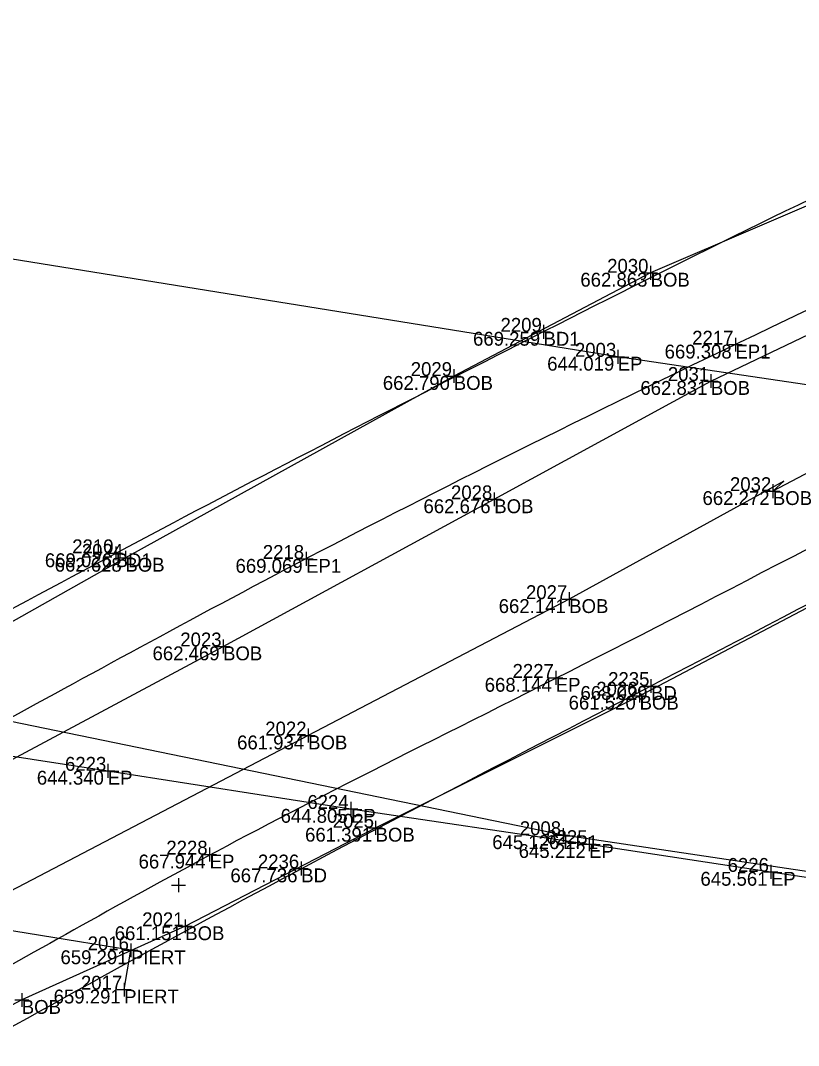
# Model space of a CAD drawing. Extents: x 2197382 to 2204062, y 634117 to 636522.
# Drawn here: x 2202828.1 to 2202884.1, y 635326 to 635399.9 of the extents above; entities that cross this region are included whole.
import ezdxf

# ---------------------------------------------------------------- set-up
doc = ezdxf.new("R2010")
doc.units = 0
for name, color, linetype in [('_CIVIL_CONSTRUCTION', 7, 'Continuous'), ('BR_X_SV_Bottom_of_Beam', 7, 'Continuous'), ('BR_X_SV_Bottom_of_Beam_Text', 7, 'Continuous'), ('BR_X_SV_Deck_Top', 7, 'Continuous'), ('BR_X_SV_Deck_Top_Text', 7, 'Continuous'), ('BR_X_SV_Pier', 7, 'Continuous'), ('BR_X_SV_Pier_Cap_Top_Text', 7, 'Continuous'), ('GE_P_Alignment_100_Distances', 7, 'Continuous'), ('SH_Border', 7, 'Continuous'), ('SH_Cut_Line', 7, 'Continuous'), ('SH_Data', 7, 'Continuous')]:
    doc.layers.add(name, color=color, linetype=linetype)

msp = doc.modelspace()

# ---------------------------------------------------------------- linework, layer by layer
at = {"layer": '_CIVIL_CONSTRUCTION'}
for p, q in [((2202873.474, 635382.191), (2202873.474, 635381.191)), ((2202872.974, 635381.691), (2202873.974, 635381.691)), ((2202873.474, 635381.691), (2202873.474, 635381.691)), ((2202865.758, 635377.935), (2202865.758, 635376.935)), ((2202865.258, 635377.435), (2202866.258, 635377.435)), ((2202865.758, 635377.435), (2202865.758, 635377.435)), ((2202879.585, 635377.009), (2202879.585, 635376.009)), ((2202871.103, 635376.135), (2202871.103, 635375.135)), ((2202879.085, 635376.509), (2202880.085, 635376.509)), ((2202879.585, 635376.509), (2202879.585, 635376.509)), ((2202870.603, 635375.635), (2202871.603, 635375.635)), ((2202871.103, 635375.635), (2202871.103, 635375.635)), ((2202859.286, 635374.749), (2202859.286, 635373.749)), ((2202858.786, 635374.249), (2202859.786, 635374.249)), ((2202859.286, 635374.249), (2202859.286, 635374.249)), ((2202877.318, 635373.889), (2202878.318, 635373.889)), ((2202877.818, 635374.389), (2202877.818, 635373.389)), ((2202877.818, 635373.889), (2202877.818, 635373.889)), ((2202882.287, 635366.45), (2202882.287, 635365.45)), ((2202862.206, 635365.861), (2202862.206, 635364.861)), ((2202881.787, 635365.95), (2202882.787, 635365.95)), ((2202882.287, 635365.95), (2202882.287, 635365.95)), ((2202861.706, 635365.361), (2202862.706, 635365.361)), ((2202862.206, 635365.361), (2202862.206, 635365.361)), ((2202834.415, 635361.468), (2202835.415, 635361.468)), ((2202834.915, 635361.968), (2202834.915, 635360.968)), ((2202834.915, 635361.468), (2202834.915, 635361.468)), ((2202835.616, 635361.644), (2202835.616, 635360.644)), ((2202848.639, 635361.563), (2202848.639, 635360.563)), ((2202835.116, 635361.144), (2202836.116, 635361.144)), ((2202835.616, 635361.144), (2202835.616, 635361.144)), ((2202848.139, 635361.063), (2202849.139, 635361.063)), ((2202848.639, 635361.063), (2202848.639, 635361.063)), ((2202867.606, 635358.664), (2202867.606, 635357.664)), ((2202867.106, 635358.164), (2202868.106, 635358.164)), ((2202867.606, 635358.164), (2202867.606, 635358.164)), ((2202842.156, 635354.754), (2202843.156, 635354.754)), ((2202842.656, 635355.254), (2202842.656, 635354.254)), ((2202842.656, 635354.754), (2202842.656, 635354.754)), ((2202866.138, 635352.488), (2202867.138, 635352.488)), ((2202866.638, 635352.988), (2202866.638, 635351.988)), ((2202866.638, 635352.488), (2202866.638, 635352.488)), ((2202873.502, 635352.401), (2202873.502, 635351.401)), ((2202872.681, 635351.702), (2202872.681, 635350.702)), ((2202873.002, 635351.901), (2202874.002, 635351.901)), ((2202873.502, 635351.901), (2202873.502, 635351.901)), ((2202872.181, 635351.202), (2202873.181, 635351.202)), ((2202872.681, 635351.202), (2202872.681, 635351.202)), ((2202848.789, 635348.833), (2202848.789, 635347.833)), ((2202848.289, 635348.333), (2202849.289, 635348.333)), ((2202848.789, 635348.333), (2202848.789, 635348.333)), ((2202833.846, 635345.79), (2202834.846, 635345.79)), ((2202834.346, 635346.29), (2202834.346, 635345.29)), ((2202834.346, 635345.79), (2202834.346, 635345.79)), ((2202851.873, 635343.542), (2202851.873, 635342.542)), ((2202851.373, 635343.042), (2202852.373, 635343.042)), ((2202851.873, 635343.042), (2202851.873, 635343.042)), ((2202853.649, 635342.182), (2202853.649, 635341.182)), ((2202853.149, 635341.682), (2202854.149, 635341.682)), ((2202853.649, 635341.682), (2202853.649, 635341.682)), ((2202867.163, 635341.647), (2202867.163, 635340.647)), ((2202866.663, 635341.147), (2202867.663, 635341.147)), ((2202867.163, 635341.147), (2202867.163, 635341.147)), ((2202869.038, 635341.006), (2202869.038, 635340.006)), ((2202841.688, 635340.248), (2202841.688, 635339.248)), ((2202868.538, 635340.506), (2202869.538, 635340.506)), ((2202869.038, 635340.506), (2202869.038, 635340.506)), ((2202841.188, 635339.748), (2202842.188, 635339.748)), ((2202841.688, 635339.748), (2202841.688, 635339.748)), ((2202848.289, 635339.249), (2202848.289, 635338.249)), ((2202847.789, 635338.749), (2202848.789, 635338.749)), ((2202848.289, 635338.749), (2202848.289, 635338.749)), ((2202881.647, 635338.503), (2202882.647, 635338.503)), ((2202882.147, 635339.003), (2202882.147, 635338.003)), ((2202882.147, 635338.503), (2202882.147, 635338.503)), ((2202839.444, 635338.041), (2202839.444, 635337.041)), ((2202838.944, 635337.541), (2202839.944, 635337.541)), ((2202839.444, 635337.541), (2202839.444, 635337.541)), ((2202839.929, 635335.08), (2202839.929, 635334.08)), ((2202839.429, 635334.58), (2202840.429, 635334.58)), ((2202839.929, 635334.58), (2202839.929, 635334.58)), ((2202836.019, 635333.348), (2202836.019, 635332.348)), ((2202835.519, 635332.848), (2202836.519, 635332.848)), ((2202836.019, 635332.848), (2202836.019, 635332.848)), ((2202835.527, 635330.515), (2202835.527, 635329.515)), ((2202828.147, 635329.766), (2202828.147, 635328.766)), ((2202835.027, 635330.015), (2202836.027, 635330.015)), ((2202835.527, 635330.015), (2202835.527, 635330.015)), ((2202827.647, 635329.266), (2202828.647, 635329.266)), ((2202828.147, 635329.266), (2202828.147, 635329.266))]:
    msp.add_line(p, q, dxfattribs=at)
at = {"layer": 'BR_X_SV_Bottom_of_Beam'}
for points in [[(2202895.149, 635391.277), (2202889.677, 635388.632), (2202873.474, 635381.691), (2202859.286, 635374.249), (2202835.616, 635361.144), (2202806.729, 635344.852)], [(2202811.504, 635338.061), (2202842.656, 635354.754), (2202862.206, 635365.361), (2202877.818, 635373.889), (2202891.444, 635380.393), (2202905.562, 635386.459), (2202910.377, 635388.736)], [(2202924.395, 635385.96), (2202919.465, 635383.68), (2202908.362, 635378.917), (2202897.213, 635373.813), (2202882.287, 635365.95), (2202883.082, 635366.661), (2202867.606, 635358.164), (2202848.789, 635348.333), (2202824.632, 635335.716)], [(2202839.929, 635334.58), (2202853.649, 635341.682), (2202872.681, 635351.202), (2202889.893, 635360.25), (2202903.168, 635366.923), (2202912.818, 635371.819), (2202920.337, 635375.101), (2202932.959, 635380.969), (2202937.114, 635382.149)], [(2202839.929, 635334.58), (2202828.147, 635329.266), (2202805.783, 635317.402), (2202793.121, 635309.278), (2202781.892, 635302.295), (2202770.512, 635294.985), (2202760.016, 635288.483), (2202748.947, 635281.46), (2202738.904, 635275.242), (2202730.251, 635269.14), (2202720.215, 635262.08), (2202711.743, 635255.569)]]:
    msp.add_lwpolyline(points, dxfattribs=at)
at = {"layer": 'BR_X_SV_Deck_Top'}
for points in [[(2202895.365, 635391.811), (2202885.347, 635387.334), (2202865.192, 635377.205), (2202839.037, 635363.762), (2202813.103, 635349.723), (2202789.18, 635336.138), (2202762.388, 635320.287), (2202740.668, 635306.565), (2202716.628, 635290.831), (2202693.394, 635275.343), (2202664.567, 635254.787), (2202633.536, 635231.765), (2202595.89, 635201.643), (2202569.397, 635178.622), (2202555.165, 635165.675)], [(2202923.181, 635376.197), (2202906.167, 635369.085), (2202881.487, 635355.934), (2202846.739, 635338.13), (2202819.013, 635322.649), (2202790.142, 635306.09), (2202754.022, 635283.778), (2202709.422, 635255.583), (2202663.285, 635220.884), (2202620.566, 635187.914), (2202595.285, 635167.396), (2202582.509, 635156.81)]]:
    msp.add_open_spline(points, degree=3, dxfattribs=at)
at = {"layer": 'BR_X_SV_Pier'}
msp.add_lwpolyline([(2202835.527, 635330.015), (2202836.019, 635332.848), (2202822.953, 635334.97), (2202822.999, 635334.938), (2202809.828, 635337.015), (2202809.889, 635336.977)], dxfattribs=at)
at = {"layer": 'GE_P_Alignment_100_Distances'}
for points in [[(2202975.789, 635361.358), (2202911.398, 635369.868), (2202894.289, 635372.201), (2202871.103, 635375.635), (2202823.555, 635383.286), (2202728.393, 635399.878)], [(2202937.002, 635329.713), (2202895.665, 635336.892), (2202867.163, 635341.147), (2202804.916, 635353.945)], [(2202818.285, 635348.253), (2202834.346, 635345.79), (2202851.873, 635343.042), (2202869.038, 635340.506), (2202882.147, 635338.503), (2202898.089, 635336.111), (2202910.08, 635334.482), (2202925.462, 635332.351), (2202937.945, 635330.578), (2202955.924, 635328.277)]]:
    msp.add_lwpolyline(points, dxfattribs=at)
for points in [[(2202926.993, 635398.223), (2202911.054, 635391.267), (2202884.78, 635379.221), (2202850.251, 635362.173), (2202828.215, 635350.038), (2202808.09, 635339.198), (2202790.855, 635329.045), (2202764, 635313.325), (2202738.781, 635297.635), (2202713.051, 635280.577), (2202697.019, 635269.602), (2202684.529, 635260.864), (2202668.986, 635249.754), (2202642.65, 635230.806), (2202596.561, 635193.887), (2202560.681, 635163.156), (2202538.312, 635142.813)], [(2202919.499, 635378.368), (2202901.447, 635370.678), (2202875.936, 635356.879), (2202844.592, 635341.598), (2202825.856, 635330.823), (2202809.466, 635322.019), (2202780.051, 635304.409), (2202746.062, 635282.999), (2202707.717, 635258.176), (2202682.244, 635240.209), (2202658.947, 635222.257), (2202614.143, 635189.251), (2202577.354, 635157.516), (2202549.508, 635131.427)]]:
    msp.add_open_spline(points, degree=3, dxfattribs=at)

# ---------------------------------------------------------------- texts
at = {"layer": 'BR_X_SV_Bottom_of_Beam_Text'}
for s, p in [('2030', (2202870.342, 635381.691)), ('662.863', (2202868.41, 635380.691)), ('BOB', (2202873.474, 635380.691)), ('2029', (2202856.184, 635374.249)), ('2031', (2202874.718, 635373.889)), ('662.790', (2202854.172, 635373.249)), ('BOB', (2202859.286, 635373.249)), ('662.831', (2202872.736, 635372.889)), ('BOB', (2202877.818, 635372.889)), ('2032', (2202879.195, 635365.95)), ('2028', (2202859.087, 635365.361)), ('662.272', (2202877.214, 635364.95)), ('BOB', (2202882.287, 635364.95)), ('662.676', (2202857.102, 635364.361)), ('BOB', (2202862.206, 635364.361)), ('2024', (2202832.475, 635361.144)), ('662.628', (2202830.516, 635360.144)), ('BOB', (2202835.616, 635360.144)), ('2027', (2202864.491, 635358.164)), ('662.141', (2202862.524, 635357.164)), ('BOB', (2202867.606, 635357.164)), ('2023', (2202839.573, 635354.754)), ('662.469', (2202837.572, 635353.754)), ('BOB', (2202842.656, 635353.754)), ('2026', (2202869.558, 635351.202)), ('661.520', (2202867.567, 635350.202)), ('BOB', (2202872.681, 635350.202)), ('2022', (2202845.697, 635348.333)), ('661.934', (2202843.667, 635347.333)), ('BOB', (2202848.789, 635347.333)), ('2025', (2202850.56, 635341.682)), ('661.391', (2202848.567, 635340.682)), ('BOB', (2202853.649, 635340.682)), ('2021', (2202836.829, 635334.58)), ('661.151', (2202834.847, 635333.58)), ('BOB', (2202839.929, 635333.58)), ('BOB', (2202828.147, 635328.266))]:
    msp.add_text(s, height=1, dxfattribs=at).set_placement(p)
at = {"layer": 'BR_X_SV_Deck_Top_Text'}
for s, p in [('2209', (2202862.656, 635377.435)), ('669.259', (2202860.674, 635376.435)), ('BD1', (2202865.758, 635376.435)), ('2210', (2202831.783, 635361.468)), ('669.026', (2202829.811, 635360.468)), ('BD1', (2202834.915, 635360.468)), ('2235', (2202870.413, 635351.901)), ('668.029', (2202868.418, 635350.901)), ('BD', (2202873.502, 635350.901)), ('2236', (2202845.166, 635338.749)), ('667.736', (2202843.185, 635337.749)), ('BD', (2202848.289, 635337.749))]:
    msp.add_text(s, height=1, dxfattribs=at).set_placement(p)
at = {"layer": 'BR_X_SV_Pier_Cap_Top_Text'}
for s, p in [('2016', (2202832.896, 635332.848)), ('659.291', (2202830.937, 635331.848)), ('PIERT', (2202836.019, 635331.848)), ('2017', (2202832.412, 635330.015)), ('659.291', (2202830.445, 635329.015)), ('PIERT', (2202835.527, 635329.015))]:
    msp.add_text(s, height=1, dxfattribs=at).set_placement(p)
at = {"layer": 'SH_Border'}
for s, p in [('EP1', (2202879.585, 635375.509)), ('EP', (2202871.103, 635374.635)), ('EP1', (2202848.639, 635360.063)), ('EP', (2202866.638, 635351.488)), ('EP', (2202834.346, 635344.79)), ('EP', (2202851.873, 635342.042)), ('EP1', (2202867.163, 635340.147)), ('EP', (2202869.038, 635339.506)), ('EP', (2202841.688, 635338.748)), ('EP', (2202882.147, 635337.503))]:
    msp.add_text(s, height=1, dxfattribs=at).set_placement(p)
at = {"layer": 'SH_Cut_Line'}
for s, p in [('2217', (2202876.47, 635376.509)), ('2003', (2202868.02, 635375.635)), ('2218', (2202845.52, 635361.063)), ('2227', (2202863.523, 635352.488)), ('6223', (2202831.263, 635345.79)), ('6224', (2202848.732, 635343.042)), ('2008', (2202864.044, 635341.147)), ('6225', (2202865.949, 635340.506)), ('2228', (2202838.569, 635339.748)), ('6226', (2202879.024, 635338.503))]:
    msp.add_text(s, height=1, dxfattribs=at).set_placement(p)
at = {"layer": 'SH_Data'}
for s, p in [('669.308', (2202874.485, 635375.509)), ('644.019', (2202866.019, 635374.635)), ('669.069', (2202843.555, 635360.063)), ('668.144', (2202861.516, 635351.488)), ('644.340', (2202829.232, 635344.79)), ('644.805', (2202846.803, 635342.042)), ('645.126', (2202862.059, 635340.147)), ('645.212', (2202863.965, 635339.506)), ('667.944', (2202836.566, 635338.748)), ('645.561', (2202877.065, 635337.503))]:
    msp.add_text(s, height=1, dxfattribs=at).set_placement(p)

doc.saveas('drawing.dxf')
